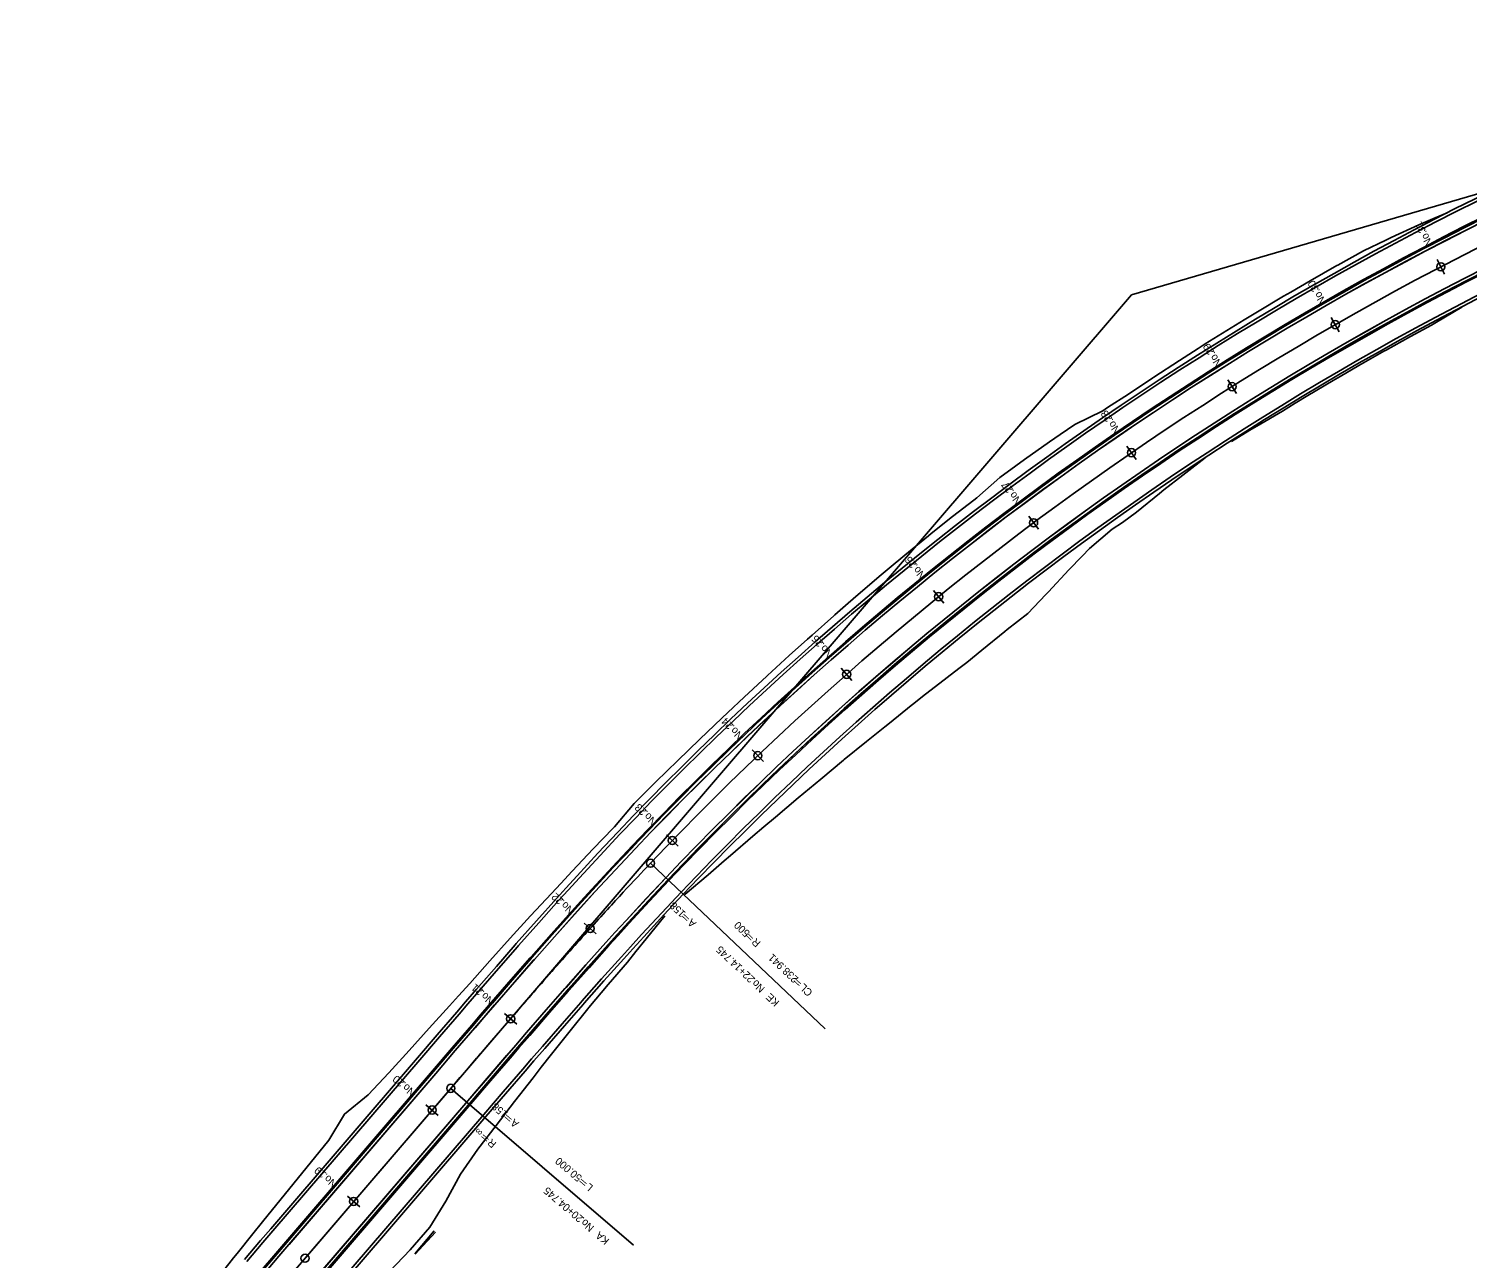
# Model space of a CAD drawing. Extents: x 46424 to 47578, y 10417 to 11548.
# Drawn here: x 46423.8 to 46662.8, y 10753 to 10957.3 of the extents above; entities that cross this region are included whole.
import ezdxf

# ---------------------------------------------------------------- set-up
doc = ezdxf.new("R2010")
doc.units = 0
for name, color, linetype in [('Default', 7, 'Continuous'), ('出典（地理院地図Vector）', 7, 'Continuous'), ('河川_人工水路(地下)（地理院地図Vector）', 7, 'Continuous'), ('現況_地形', 7, 'Continuous'), ('現況_地形_三角形', 7, 'Continuous'), ('現況_地形_三角形_頂点', 7, 'Continuous'), ('現況_地形_低い点', 7, 'Continuous'), ('現況_地形_単点標高', 7, 'Continuous'), ('現況_地形_等高線_マイナー', 7, 'Continuous'), ('等高線等深線_等高線_補助曲線通常部（地理院地図Vector）', 7, 'Continuous'), ('設計図面_測点 ラベル メジャー', 7, 'Continuous'), ('設計図面_測点 印 メジャー', 7, 'Continuous')]:
    doc.layers.add(name, color=color, linetype=linetype)

msp = doc.modelspace()

# ---------------------------------------------------------------- linework, layer by layer
at = {"layer": 'Default'}
for p, q in [((46606.99, 10913.06), (47182.22, 11080.85)), ((46658.39, 10917.72), (46658.39, 10917.72)), ((46423.8, 10699.52), (46606.99, 10913.06)), ((46640.85, 10908.11), (46640.85, 10908.11)), ((46623.71, 10897.81), (46623.71, 10897.81)), ((46606.99, 10886.83), (46606.99, 10886.83)), ((46590.73, 10875.19), (46590.73, 10875.19)), ((46574.95, 10862.91), (46574.95, 10862.91)), ((46559.67, 10850.01), (46559.67, 10850.01)), ((46544.91, 10836.5), (46544.91, 10836.5)), ((46530.71, 10822.42), (46530.71, 10822.42)), ((46527.08, 10818.63), (46527.08, 10818.63)), ((46527.08, 10818.63), (46556.1, 10791.1)), ((46527.08, 10818.63), (46556.1, 10791.1)), ((46517.07, 10807.8), (46517.07, 10807.8)), ((46503.85, 10792.79), (46503.85, 10792.79)), ((46469.69, 10753.01), (46493.9, 10781.23)), ((46493.9, 10781.23), (46493.9, 10781.23)), ((46493.9, 10781.23), (46524.25, 10755.19)), ((46490.81, 10777.63), (46490.81, 10777.63)), ((46477.78, 10762.45), (46477.78, 10762.45)), ((46469.69, 10753.01), (46469.69, 10753.01))]:
    msp.add_line(p, q, dxfattribs=at)
for centre in [(46658.39, 10917.72), (46640.85, 10908.11), (46623.71, 10897.81), (46606.99, 10886.83), (46590.73, 10875.19), (46574.95, 10862.91), (46559.67, 10850.01), (46544.91, 10836.5), (46530.71, 10822.42), (46527.08, 10818.63), (46517.07, 10807.8), (46503.85, 10792.79), (46493.9, 10781.23), (46490.81, 10777.63), (46477.78, 10762.45), (46469.69, 10753.01)]:
    msp.add_circle(centre, 0.675, dxfattribs=at)
msp.add_arc((46889.81, 10474.5), 500, 109.127, 136.5076, dxfattribs=at)
msp.add_arc((46889.81, 10474.5), 500, 109.127, 136.5076, dxfattribs=at)
msp.add_open_spline([(46493.9, 10781.23), (46495.25, 10782.81), (46497.97, 10785.98), (46503.4, 10792.29), (46510.23, 10800.16), (46517.16, 10807.93), (46522.79, 10814.08), (46525.64, 10817.12), (46527.08, 10818.63)], degree=3, dxfattribs=at)
msp.add_open_spline([(46493.9, 10781.23), (46495.25, 10782.81), (46497.97, 10785.98), (46503.4, 10792.29), (46510.23, 10800.16), (46517.16, 10807.93), (46522.79, 10814.08), (46525.64, 10817.12), (46527.08, 10818.63)], degree=3, dxfattribs=at)
at = {"layer": '出典（地理院地図Vector）'}
for points in [[(46459.63, 10752.78), (46462.32, 10755.94), (46463.99, 10757.9), (46488.37, 10786.31), (46491.63, 10790.11), (46494.9, 10793.91), (46496.37, 10795.61), (46498.18, 10797.7), (46501.48, 10801.5), (46504.62, 10805.09), (46504.79, 10805.28), (46508.13, 10809.06), (46511.5, 10812.82), (46513.03, 10814.5), (46514.9, 10816.56), (46518.34, 10820.28), (46521.64, 10823.79)], [(46475.38, 10748.13), (46499.75, 10776.54), (46503.01, 10780.33), (46506.26, 10784.11), (46507.72, 10785.81), (46509.52, 10787.88), (46512.78, 10791.64), (46515.88, 10795.18), (46516.05, 10795.37), (46519.34, 10799.09), (46522.64, 10802.77), (46524.13, 10804.42), (46525.97, 10806.43), (46529.31, 10810.06), (46532.52, 10813.47)]]:
    msp.add_lwpolyline(points, dxfattribs=at)
for radius in [507.5, 492.5]:
    msp.add_arc((46889.81, 10474.5), radius, 109.127, 136.5076, dxfattribs=at)
at = {"layer": '河川_人工水路(地下)（地理院地図Vector）'}
msp.add_line((46469.69, 10753.01), (46493.9, 10781.23), dxfattribs=at)
msp.add_arc((46889.81, 10474.5), 500, 109.127, 136.5076, dxfattribs=at)
msp.add_open_spline([(46493.9, 10781.23), (46495.25, 10782.81), (46497.97, 10785.98), (46503.4, 10792.29), (46510.23, 10800.16), (46517.16, 10807.93), (46522.79, 10814.08), (46525.64, 10817.12), (46527.08, 10818.63)], degree=3, dxfattribs=at)
at = {"layer": '現況_地形'}
for points in [[(46462.68, 10750.2), (46465.36, 10753.34), (46467.03, 10755.29), (46491.41, 10783.7), (46494.66, 10787.5), (46497.93, 10791.29), (46499.4, 10793), (46501.2, 10795.09), (46504.49, 10798.87), (46507.63, 10802.45), (46507.79, 10802.64), (46511.12, 10806.4), (46514.47, 10810.14), (46515.99, 10811.81), (46517.85, 10813.86), (46521.27, 10817.56), (46524.54, 10821.04)], [(46462.68, 10750.21), (46465.35, 10753.35), (46467.02, 10755.3), (46491.4, 10783.71), (46494.66, 10787.51), (46497.92, 10791.3), (46499.39, 10793), (46501.19, 10795.09), (46504.48, 10798.88), (46507.62, 10802.46), (46507.79, 10802.65), (46511.11, 10806.41), (46514.47, 10810.15), (46515.98, 10811.82), (46517.85, 10813.87), (46521.26, 10817.56), (46524.53, 10821.04)], [(46472.34, 10750.73), (46496.72, 10779.15), (46499.97, 10782.94), (46503.23, 10786.73), (46504.69, 10788.42), (46506.49, 10790.5), (46509.76, 10794.27), (46512.88, 10797.83), (46513.05, 10798.02), (46516.35, 10801.75), (46519.67, 10805.45), (46521.17, 10807.11), (46523.02, 10809.13), (46526.39, 10812.78), (46529.62, 10816.22)], [(46472.35, 10750.73), (46496.73, 10779.14), (46499.98, 10782.93), (46503.24, 10786.72), (46504.7, 10788.42), (46506.5, 10790.5), (46509.77, 10794.26), (46512.89, 10797.82), (46513.06, 10798.01), (46516.36, 10801.74), (46519.68, 10805.45), (46521.18, 10807.1), (46523.02, 10809.13), (46526.4, 10812.78), (46529.62, 10816.21)]]:
    msp.add_lwpolyline(points, dxfattribs=at)
for radius in [503.51, 503.5, 496.5, 496.49]:
    msp.add_arc((46889.81, 10474.5), radius, 109.127, 136.5076, dxfattribs=at)
at = {"layer": '現況_地形_三角形'}
for p, q in [((46487.92, 10753.76), (46491.17, 10757.55)), ((46487.97, 10753.71), (46491.38, 10757.37))]:
    msp.add_line(p, q, dxfattribs=at)
for points in [[(46454.66, 10749.02), (46457.83, 10753.1), (46458.4, 10753.82), (46461.01, 10757.06), (46462.63, 10759.06), (46473.64, 10772.6), (46476.23, 10776.96), (46480.19, 10780.15), (46483.61, 10783.81), (46486.97, 10787.51), (46490.33, 10791.22), (46493.69, 10794.94), (46495.2, 10796.62), (46497.05, 10798.68), (46500.41, 10802.42), (46503.78, 10806.17), (46507.17, 10809.92), (46510.62, 10813.62), (46512.17, 10815.28), (46514.08, 10817.31), (46517.57, 10821), (46520.91, 10824.48), (46521.08, 10824.68), (46524.39, 10828.55), (46526.97, 10831.14), (46527.99, 10832.14), (46531.62, 10835.71), (46533.4, 10837.44), (46535.27, 10839.25), (46538.95, 10842.76), (46539.91, 10843.66), (46542.66, 10846.24), (46546.39, 10849.7), (46546.5, 10849.8), (46550.14, 10853.13), (46553.16, 10855.86), (46553.92, 10856.54), (46557.53, 10859.75), (46557.73, 10859.92), (46559.9, 10861.82), (46561.56, 10863.26), (46565.43, 10866.56), (46566.75, 10867.67), (46569.34, 10869.82), (46573.28, 10873.04), (46573.71, 10873.39), (46577.26, 10876.22), (46580.8, 10878.95), (46581.31, 10879.31), (46585.13, 10882.69), (46587.78, 10884.66), (46589.23, 10885.71), (46593.39, 10888.65), (46595.14, 10889.86), (46597.59, 10891.54), (46602.21, 10893.8), (46603.01, 10894.32), (46606.47, 10896.57), (46610.53, 10899.27), (46610.71, 10899.39), (46614.97, 10902.16), (46618.08, 10904.16), (46619.25, 10904.9), (46623.57, 10907.58), (46625.73, 10908.91), (46627.91, 10910.23), (46632.27, 10912.83), (46633.45, 10913.52), (46636.67, 10915.39), (46641.09, 10917.91), (46641.25, 10918), (46645.53, 10920.38), (46649.24, 10922.15), (46650.12, 10922.57), (46654.75, 10924.69), (46657.44, 10925.87), (46659.42, 10926.7)], [(46623.61, 10888.72), (46626.68, 10890.57), (46627.83, 10891.26), (46632.06, 10893.76), (46634.16, 10895.04), (46636.27, 10896.32), (46640.5, 10898.83), (46641.64, 10899.5), (46644.76, 10901.31), (46649.03, 10903.74), (46649.2, 10903.83), (46653.33, 10906.14), (46656.82, 10908.04), (46657.65, 10908.5), (46661.9, 10910.99)], [(46476.2, 10744.06), (46477.93, 10745.94), (46479.83, 10747.52), (46483.7, 10750.79), (46487.16, 10754.41), (46490.41, 10758.2), (46493.07, 10762.51), (46495.53, 10766.99), (46498.41, 10771.11), (46501.45, 10775.08), (46504.5, 10779.05), (46507.57, 10782.99), (46508.94, 10784.75), (46510.64, 10786.91), (46513.74, 10790.8), (46516.69, 10794.47), (46516.85, 10794.67), (46520.03, 10798.47), (46523.26, 10802.22), (46524.65, 10803.95), (46526.35, 10806.08), (46529.46, 10809.92)]]:
    msp.add_lwpolyline(points, dxfattribs=at)
at = {"layer": '現況_地形_三角形_頂点'}
msp.add_lwpolyline([(46532.67, 10813.32), (46532.87, 10813.47), (46536.64, 10816.68), (46539.32, 10819.01), (46540.36, 10819.91), (46544.1, 10823.13), (46545.93, 10824.69), (46547.85, 10826.31), (46551.61, 10829.48), (46552.58, 10830.3), (46555.38, 10832.62), (46559.16, 10835.75), (46559.27, 10835.84), (46562.96, 10838.85), (46566, 10841.31), (46566.77, 10841.93), (46570.4, 10844.83), (46570.59, 10844.98), (46572.78, 10846.71), (46574.44, 10848.01), (46578.33, 10850.98), (46579.64, 10851.99), (46582.13, 10854.05), (46585.93, 10857.12), (46586.35, 10857.45), (46589.77, 10860.14), (46592.77, 10863.29), (46593.18, 10863.73), (46596.58, 10867.35), (46598.82, 10869.67), (46600.04, 10870.92), (46603.79, 10874.12), (46605.51, 10875.26), (46607.8, 10876.97), (46611.63, 10880.07), (46612.36, 10880.64), (46615.51, 10883.12), (46619.26, 10886), (46619.42, 10886.12)], dxfattribs=at)
at = {"layer": '現況_地形_低い点'}
for points in [[(46462.3, 10750.52), (46464.98, 10753.67), (46466.65, 10755.62), (46491.03, 10784.03), (46494.28, 10787.83), (46497.55, 10791.62), (46499.02, 10793.32), (46500.82, 10795.41), (46504.11, 10799.2), (46507.25, 10802.78), (46507.42, 10802.97), (46510.75, 10806.73), (46514.1, 10810.48), (46515.62, 10812.15), (46517.49, 10814.2), (46520.9, 10817.9), (46524.18, 10821.38)], [(46472.72, 10750.41), (46497.1, 10778.82), (46500.35, 10782.61), (46503.61, 10786.4), (46505.07, 10788.1), (46506.87, 10790.18), (46510.14, 10793.94), (46513.26, 10797.5), (46513.42, 10797.69), (46516.72, 10801.41), (46520.04, 10805.12), (46521.54, 10806.77), (46523.38, 10808.8), (46526.75, 10812.44), (46529.98, 10815.88)]]:
    msp.add_lwpolyline(points, dxfattribs=at)
for radius in [504, 496]:
    msp.add_arc((46889.81, 10474.5), radius, 109.127, 136.5076, dxfattribs=at)
at = {"layer": '現況_地形_単点標高'}
for points in [[(46460.01, 10752.46), (46462.7, 10755.62), (46464.37, 10757.57), (46488.75, 10785.98), (46492.01, 10789.78), (46495.28, 10793.58), (46496.75, 10795.29), (46498.56, 10797.38), (46501.85, 10801.17), (46505, 10804.76), (46505.17, 10804.95), (46508.51, 10808.73), (46511.87, 10812.49), (46513.4, 10814.17), (46515.27, 10816.23), (46518.71, 10819.94), (46522, 10823.45)], [(46462.15, 10750.65), (46464.83, 10753.8), (46466.5, 10755.75), (46490.87, 10784.16), (46494.13, 10787.96), (46497.4, 10791.75), (46498.87, 10793.46), (46500.67, 10795.54), (46503.96, 10799.33), (46507.1, 10802.91), (46507.27, 10803.1), (46510.6, 10806.87), (46513.95, 10810.61), (46515.47, 10812.29), (46517.34, 10814.33), (46520.75, 10818.03), (46524.03, 10821.52)], [(46472.87, 10750.28), (46497.25, 10778.69), (46500.5, 10782.48), (46503.76, 10786.27), (46505.22, 10787.97), (46507.02, 10790.04), (46510.29, 10793.81), (46513.41, 10797.36), (46513.57, 10797.55), (46516.87, 10801.28), (46520.19, 10804.98), (46521.69, 10806.64), (46523.53, 10808.66), (46526.9, 10812.31), (46530.12, 10815.74)], [(46475, 10748.46), (46499.37, 10776.87), (46502.63, 10780.66), (46505.88, 10784.44), (46507.34, 10786.14), (46509.14, 10788.21), (46512.4, 10791.97), (46515.51, 10795.51), (46515.68, 10795.7), (46518.96, 10799.42), (46522.27, 10803.11), (46523.76, 10804.76), (46525.6, 10806.77), (46528.95, 10810.4), (46532.16, 10813.81)]]:
    msp.add_lwpolyline(points, dxfattribs=at)
for radius in [507, 504.2, 495.8, 493]:
    msp.add_arc((46889.81, 10474.5), radius, 109.127, 136.5076, dxfattribs=at)
at = {"layer": '現況_地形_等高線_マイナー'}
for points in [[(46462.29, 10750.54), (46464.96, 10753.68), (46466.64, 10755.63), (46491.01, 10784.04), (46494.27, 10787.84), (46497.53, 10791.63), (46499, 10793.34), (46500.81, 10795.43), (46504.1, 10799.21), (46507.24, 10802.79), (46507.4, 10802.99), (46510.73, 10806.75), (46514.09, 10810.49), (46515.6, 10812.16), (46517.47, 10814.21), (46520.89, 10817.91), (46524.16, 10821.39)], [(46472.74, 10750.4), (46497.11, 10778.81), (46500.37, 10782.6), (46503.62, 10786.39), (46505.09, 10788.08), (46506.89, 10790.16), (46510.16, 10793.93), (46513.27, 10797.48), (46513.44, 10797.67), (46516.74, 10801.4), (46520.06, 10805.1), (46521.56, 10806.76), (46523.4, 10808.78), (46526.77, 10812.43), (46529.99, 10815.86)]]:
    msp.add_lwpolyline(points, dxfattribs=at)
for radius in [504.02, 495.98]:
    msp.add_arc((46889.81, 10474.5), radius, 109.127, 136.5076, dxfattribs=at)
at = {"layer": '等高線等深線_等高線_補助曲線通常部（地理院地図Vector）'}
msp.add_line((46469.69, 10753.01), (46493.9, 10781.23), dxfattribs=at)
msp.add_arc((46889.81, 10474.5), 500, 109.127, 136.5076, dxfattribs=at)
msp.add_open_spline([(46493.9, 10781.23), (46495.25, 10782.81), (46497.97, 10785.98), (46503.4, 10792.29), (46510.23, 10800.16), (46517.16, 10807.93), (46522.79, 10814.08), (46525.64, 10817.12), (46527.08, 10818.63)], degree=3, dxfattribs=at)
at = {"layer": '設計図面_測点 印 メジャー'}
for p, q in [((46657.76, 10918.92), (46659.01, 10916.52)), ((46640.18, 10909.28), (46641.52, 10906.94)), ((46622.99, 10898.95), (46624.43, 10896.66)), ((46606.23, 10887.94), (46607.76, 10885.71)), ((46589.92, 10876.27), (46591.54, 10874.11)), ((46574.1, 10863.96), (46575.8, 10861.86)), ((46558.78, 10851.02), (46560.56, 10848.99)), ((46543.98, 10837.48), (46545.85, 10835.53)), ((46529.74, 10823.36), (46531.68, 10821.48)), ((46516.07, 10808.7), (46518.07, 10806.89)), ((46502.83, 10793.68), (46504.87, 10791.91)), ((46489.78, 10778.51), (46491.83, 10776.75)), ((46476.76, 10763.33), (46478.81, 10761.57))]:
    msp.add_line(p, q, dxfattribs=at)

# ---------------------------------------------------------------- texts
at = {"layer": 'Default'}
for s, rotation, p in [('158', 136.5076, (46533.01, 10810.41)), ('A＝', 136.5076, (46534.78, 10808.74)), ('500', 136.5076, (46543.71, 10807.15)), ('R＝', 136.5076, (46545.48, 10805.47)), ('22+14.745', 136.5076, (46544.48, 10799.54)), ('238.941', 136.5076, (46551.76, 10799.52)), ('\u3000No.', 136.5076, (46547.42, 10796.74)), ('CL＝', 136.5076, (46554.12, 10797.28)), ('KE', 136.5076, (46548.6, 10795.62)), ('158', 139.3724, (46503.49, 10777.12)), ('A＝', 139.3724, (46505.34, 10775.53)), ('R＝∞', 139.3724, (46501.59, 10772.16)), ('50.000', 139.3724, (46515.81, 10766.55)), ('L＝', 139.3724, (46517.66, 10764.97)), ('20+04.745', 139.3724, (46516.02, 10759.78)), ('\u3000No.', 139.3724, (46519.11, 10757.13)), ('KA', 139.3724, (46520.34, 10756.08))]:
    msp.add_text(s, height=1.25, rotation=rotation, dxfattribs=at).set_placement(p)
at = {"layer": '設計図面_測点 ラベル メジャー'}
for s, rotation, p in [('31', 117.5708, (46655.96, 10923.71)), ('No.', 117.5708, (46657.09, 10921.55)), ('30', 119.8627, (46638.19, 10914)), ('No.', 119.8627, (46639.4, 10911.89)), ('29', 122.1545, (46620.81, 10903.59)), ('No.', 122.1545, (46622.11, 10901.53)), ('28', 124.4463, (46603.87, 10892.49)), ('No.', 124.4463, (46605.25, 10890.48)), ('27', 126.7382, (46587.38, 10880.72)), ('No.', 126.7382, (46588.84, 10878.77)), ('26', 129.03, (46571.38, 10868.3)), ('No.', 129.03, (46572.91, 10866.41)), ('25', 131.3218, (46555.89, 10855.25)), ('No.', 131.3218, (46557.49, 10853.42)), ('24', 133.6137, (46540.93, 10841.59)), ('No.', 133.6137, (46542.61, 10839.83)), ('23', 135.9055, (46526.53, 10827.35)), ('No.', 135.9055, (46528.28, 10825.65)), ('22', 137.9482, (46512.71, 10812.57)), ('No.', 137.9482, (46514.52, 10810.94)), ('21', 139.1058, (46499.39, 10797.48)), ('No.', 139.1058, (46501.23, 10795.89)), ('20', 139.3724, (46486.33, 10782.3)), ('No.', 139.3724, (46488.18, 10780.71)), ('19', 139.3724, (46473.31, 10767.12)), ('No.', 139.3724, (46475.15, 10765.53))]:
    msp.add_text(s, height=1.25, rotation=rotation, dxfattribs=at).set_placement(p)

doc.saveas('drawing.dxf')
